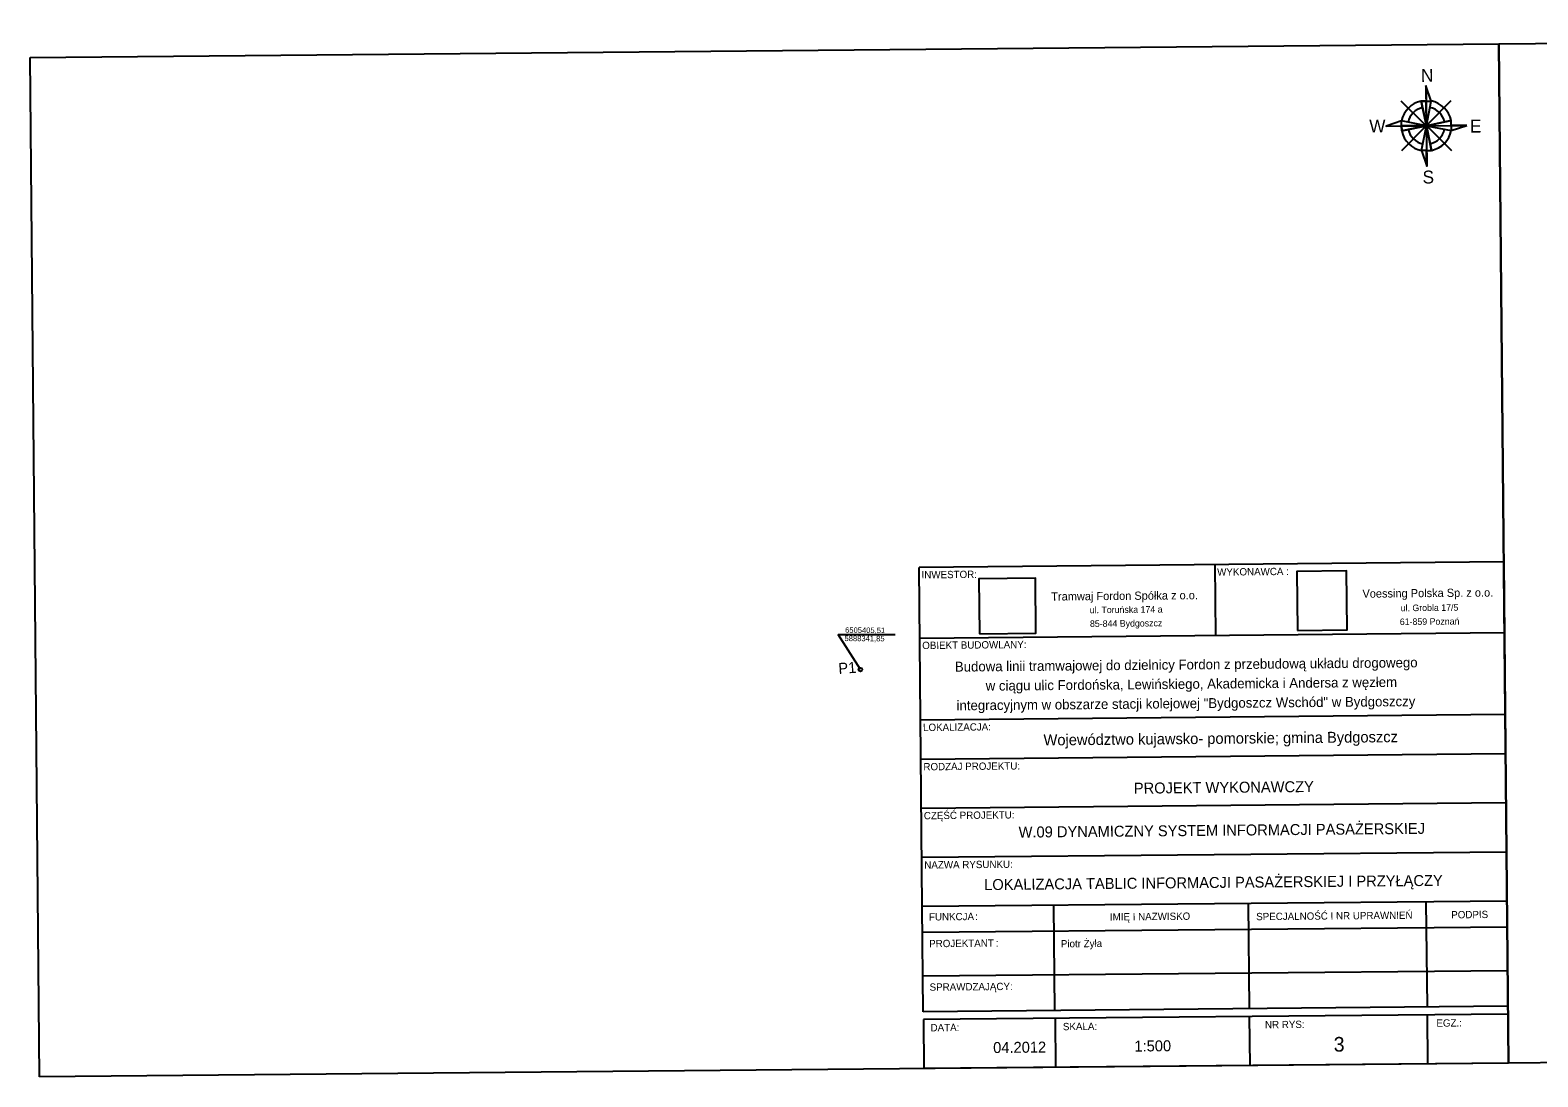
# Model space of a CAD drawing. Extents: x 6505045 to 6511721, y 5887996 to 5893535.
# Drawn here: x 6505291.9 to 6505498.2, y 5888286.1 to 5888429.3 of the extents above; entities that cross this region are included whole.
import ezdxf

# ---------------------------------------------------------------- set-up
doc = ezdxf.new("R2010")
doc.units = 0
for name, color, linetype in [('__legenda', 7, 'Continuous'), ('Default', 7, 'Continuous'), ('P_opisy', 7, 'Continuous'), ('P_przylacze', 7, 'Continuous'), ('P_tabela', 7, 'Continuous'), ('P_wsporzedne', 7, 'Continuous'), ('P_znak północy', 7, 'Continuous'), ('SA_Linie-020', 7, 'Continuous'), ('SA_Stempel_Text-020', 7, 'Continuous'), ('SA_Stempel_Text-030', 7, 'Continuous'), ('SA_Stempel_Text-035', 7, 'Continuous'), ('SA_Unterschrift_Text', 7, 'Continuous')]:
    doc.layers.add(name, color=color, linetype=linetype)

msp = doc.modelspace()

# ---------------------------------------------------------------- linework, layer by layer
at = {"layer": '__legenda'}
msp.add_lwpolyline([(6505465.32, 5888347.21), (6505472.12, 5888347.28), (6505472.04, 5888355.35), (6505465.24, 5888355.28)], close=True, dxfattribs=at)
at = {"layer": 'Default'}
msp.add_lwpolyline([(6505421.79, 5888346.75), (6505429.53, 5888346.82), (6505429.46, 5888354.35), (6505421.72, 5888354.28)], close=True, dxfattribs=at)
at = {"layer": 'P_przylacze'}
msp.add_circle((6505405.51, 5888341.85), 0.25, dxfattribs=at)
at = {"layer": 'P_tabela'}
for p, q in [((6505492.87, 5888427.46), (6505693.86, 5888429.33)), ((6505492.87, 5888427.46), (6505693.86, 5888429.33)), ((6505492.87, 5888427.46), (6505693.86, 5888429.33)), ((6505291.89, 5888425.58), (6505492.87, 5888427.46)), ((6505291.89, 5888425.58), (6505492.87, 5888427.46)), ((6505291.89, 5888425.58), (6505492.87, 5888427.46)), ((6505494.18, 5888288.01), (6505492.87, 5888427.46)), ((6505492.87, 5888427.46), (6505494.18, 5888288.01)), ((6505494.18, 5888288.01), (6505492.87, 5888427.46)), ((6505492.87, 5888427.46), (6505494.18, 5888288.01)), ((6505492.87, 5888427.46), (6505494.18, 5888288.01)), ((6505494.18, 5888288.01), (6505492.87, 5888427.46)), ((6505293.19, 5888286.13), (6505291.89, 5888425.58)), ((6505293.19, 5888286.13), (6505291.89, 5888425.58)), ((6505293.19, 5888286.13), (6505291.89, 5888425.58)), ((6505695.16, 5888289.89), (6505494.18, 5888288.01)), ((6505695.16, 5888289.89), (6505494.18, 5888288.01)), ((6505695.16, 5888289.89), (6505494.18, 5888288.01)), ((6505494.18, 5888288.01), (6505293.19, 5888286.13)), ((6505494.18, 5888288.01), (6505293.19, 5888286.13)), ((6505494.18, 5888288.01), (6505293.19, 5888286.13))]:
    msp.add_line(p, q, dxfattribs=at)
at = {"layer": 'P_wsporzedne'}
for p, q in [((6505405.51, 5888341.85), (6505402.48, 5888346.63)), ((6505402.48, 5888346.63), (6505410.25, 5888346.63))]:
    msp.add_line(p, q, dxfattribs=at)
at = {"layer": 'P_znak północy'}
for p, q in [((6505482.9, 5888421.78), (6505483, 5888410.74)), ((6505482.9, 5888421.78), (6505483, 5888410.74)), ((6505482.9, 5888421.78), (6505483, 5888410.74)), ((6505482.94, 5888416.26), (6505479.51, 5888419.64)), ((6505482.94, 5888416.26), (6505479.51, 5888419.64)), ((6505482.94, 5888416.26), (6505479.51, 5888419.64)), ((6505482.23, 5888419.63), (6505482.92, 5888419.64)), ((6505482.23, 5888419.63), (6505482.92, 5888419.64)), ((6505482.23, 5888419.63), (6505482.92, 5888419.64)), ((6505482.95, 5888416.26), (6505482.23, 5888419.63)), ((6505482.95, 5888416.26), (6505482.23, 5888419.63)), ((6505482.95, 5888416.26), (6505482.23, 5888419.63)), ((6505482.92, 5888419.64), (6505483.61, 5888419.64)), ((6505482.92, 5888419.64), (6505483.61, 5888419.64)), ((6505482.92, 5888419.64), (6505483.61, 5888419.64)), ((6505482.95, 5888416.27), (6505486.34, 5888419.71)), ((6505482.95, 5888416.27), (6505486.34, 5888419.71)), ((6505482.95, 5888416.27), (6505486.34, 5888419.71)), ((6505482.95, 5888416.26), (6505483.61, 5888419.64)), ((6505482.95, 5888416.26), (6505483.61, 5888419.64)), ((6505482.95, 5888416.26), (6505483.61, 5888419.64)), ((6505477.43, 5888416.21), (6505488.47, 5888416.31)), ((6505477.43, 5888416.21), (6505488.47, 5888416.31)), ((6505477.43, 5888416.21), (6505488.47, 5888416.31)), ((6505482.95, 5888416.26), (6505479.57, 5888416.92)), ((6505482.95, 5888416.26), (6505479.57, 5888416.92)), ((6505482.95, 5888416.26), (6505479.57, 5888416.92)), ((6505482.95, 5888416.27), (6505479.57, 5888412.81)), ((6505482.95, 5888416.27), (6505479.57, 5888412.81)), ((6505482.95, 5888416.27), (6505479.57, 5888412.81)), ((6505479.57, 5888416.23), (6505482.94, 5888416.26)), ((6505479.57, 5888416.23), (6505482.94, 5888416.26)), ((6505479.57, 5888416.23), (6505482.94, 5888416.26)), ((6505479.58, 5888415.54), (6505479.57, 5888416.23)), ((6505479.58, 5888415.54), (6505479.57, 5888416.23)), ((6505479.58, 5888415.54), (6505479.57, 5888416.23)), ((6505479.58, 5888415.54), (6505482.95, 5888416.26)), ((6505482.94, 5888416.26), (6505479.58, 5888415.54)), ((6505479.58, 5888415.54), (6505482.95, 5888416.26)), ((6505482.94, 5888416.26), (6505479.58, 5888415.54)), ((6505479.58, 5888415.54), (6505482.95, 5888416.26)), ((6505482.94, 5888416.26), (6505479.58, 5888415.54)), ((6505482.29, 5888412.87), (6505482.95, 5888416.26)), ((6505482.29, 5888412.87), (6505482.95, 5888416.26)), ((6505482.29, 5888412.87), (6505482.95, 5888416.26)), ((6505482.95, 5888416.26), (6505486.33, 5888416.98)), ((6505482.95, 5888416.26), (6505486.33, 5888416.98)), ((6505482.95, 5888416.26), (6505486.33, 5888416.98)), ((6505482.95, 5888416.27), (6505486.4, 5888412.88)), ((6505482.95, 5888416.27), (6505486.4, 5888412.88)), ((6505482.95, 5888416.27), (6505486.4, 5888412.88)), ((6505482.95, 5888416.26), (6505486.34, 5888415.6)), ((6505482.95, 5888416.26), (6505483.67, 5888412.89)), ((6505482.95, 5888416.26), (6505486.34, 5888415.6)), ((6505482.95, 5888416.26), (6505483.67, 5888412.89)), ((6505482.95, 5888416.26), (6505486.34, 5888415.6)), ((6505482.95, 5888416.26), (6505483.67, 5888412.89))]:
    msp.add_line(p, q, dxfattribs=at)
for points in [[(6505482.9, 5888421.78), (6505482.92, 5888419.64), (6505482.92, 5888419.64), (6505483.61, 5888419.64), (6505482.9, 5888421.78)], [(6505482.9, 5888421.78), (6505482.92, 5888419.64), (6505482.92, 5888419.64), (6505483.61, 5888419.64), (6505482.9, 5888421.78)], [(6505482.9, 5888421.78), (6505482.92, 5888419.64), (6505482.92, 5888419.64), (6505483.61, 5888419.64), (6505482.9, 5888421.78)], [(6505482.95, 5888416.27), (6505482.92, 5888419.64), (6505482.23, 5888419.63), (6505482.95, 5888416.26), (6505482.95, 5888416.27)], [(6505482.95, 5888416.27), (6505482.92, 5888419.64), (6505482.23, 5888419.63), (6505482.95, 5888416.26), (6505482.95, 5888416.27)], [(6505482.95, 5888416.27), (6505482.92, 5888419.64), (6505482.23, 5888419.63), (6505482.95, 5888416.26), (6505482.95, 5888416.27)], [(6505479.57, 5888416.23), (6505479.57, 5888416.92), (6505477.43, 5888416.21), (6505479.57, 5888416.23)], [(6505479.57, 5888416.23), (6505479.57, 5888416.92), (6505477.43, 5888416.21), (6505479.57, 5888416.23)], [(6505479.57, 5888416.23), (6505479.57, 5888416.92), (6505477.43, 5888416.21), (6505479.57, 5888416.23)], [(6505482.94, 5888416.26), (6505479.57, 5888416.23), (6505479.58, 5888415.54), (6505482.94, 5888416.26)], [(6505482.94, 5888416.26), (6505479.57, 5888416.23), (6505479.58, 5888415.54), (6505482.94, 5888416.26)], [(6505482.94, 5888416.26), (6505479.57, 5888416.23), (6505479.58, 5888415.54), (6505482.94, 5888416.26)], [(6505482.95, 5888416.26), (6505482.95, 5888416.26), (6505482.96, 5888416.26), (6505486.33, 5888416.29), (6505486.33, 5888416.98), (6505482.95, 5888416.26)], [(6505482.95, 5888416.26), (6505482.95, 5888416.26), (6505482.96, 5888416.26), (6505486.33, 5888416.29), (6505486.33, 5888416.98), (6505482.95, 5888416.26)], [(6505482.95, 5888416.26), (6505482.95, 5888416.26), (6505482.96, 5888416.26), (6505486.33, 5888416.29), (6505486.33, 5888416.98), (6505482.95, 5888416.26)], [(6505482.98, 5888412.88), (6505483.67, 5888412.89), (6505482.95, 5888416.25), (6505482.98, 5888412.88)], [(6505482.98, 5888412.88), (6505483.67, 5888412.89), (6505482.95, 5888416.25), (6505482.98, 5888412.88)], [(6505482.98, 5888412.88), (6505483.67, 5888412.89), (6505482.95, 5888416.25), (6505482.98, 5888412.88)], [(6505488.47, 5888416.31), (6505486.33, 5888416.29), (6505486.34, 5888415.6), (6505488.47, 5888416.31)], [(6505488.47, 5888416.31), (6505486.33, 5888416.29), (6505486.34, 5888415.6), (6505488.47, 5888416.31)], [(6505488.47, 5888416.31), (6505486.33, 5888416.29), (6505486.34, 5888415.6), (6505488.47, 5888416.31)], [(6505482.98, 5888412.88), (6505482.29, 5888412.87), (6505483, 5888410.74), (6505482.98, 5888412.88)], [(6505482.98, 5888412.88), (6505482.29, 5888412.87), (6505483, 5888410.74), (6505482.98, 5888412.88)], [(6505482.98, 5888412.88), (6505482.29, 5888412.87), (6505483, 5888410.74), (6505482.98, 5888412.88)]]:
    msp.add_lwpolyline(points, dxfattribs=at)
for centre, radius, start, end in [((6505482.95, 5888416.26), 3.45, 102.0474, 168.9738), ((6505482.95, 5888416.26), 3.45, 102.0474, 168.9738), ((6505482.95, 5888416.26), 3.45, 102.0474, 168.9738), ((6505482.96, 5888416.26), 3.45, 12.0554, 79.0163), ((6505482.96, 5888416.26), 3.45, 12.0554, 79.0163), ((6505482.96, 5888416.26), 3.45, 12.0554, 79.0163), ((6505482.95, 5888416.27), 2.53, 102.1671, 169.2958), ((6505482.95, 5888416.27), 2.53, 102.1671, 169.2958), ((6505482.95, 5888416.27), 2.53, 102.1671, 169.2958), ((6505482.95, 5888416.27), 2.53, 11.7816, 78.9353), ((6505482.95, 5888416.27), 2.53, 11.7816, 78.9353), ((6505482.95, 5888416.27), 2.53, 11.7816, 78.9353), ((6505482.95, 5888416.26), 3.45, 192.0538, 259.0158), ((6505482.95, 5888416.26), 3.45, 192.0538, 259.0158), ((6505482.95, 5888416.26), 3.45, 192.0538, 259.0158), ((6505482.95, 5888416.27), 2.53, 192.3917, 259.0318), ((6505482.95, 5888416.27), 2.53, 192.3917, 259.0318), ((6505482.95, 5888416.27), 2.53, 192.3917, 259.0318), ((6505482.95, 5888416.27), 2.53, 282.0081, 348.6723), ((6505482.95, 5888416.27), 2.53, 282.0081, 348.6723), ((6505482.95, 5888416.27), 2.53, 282.0081, 348.6723), ((6505482.96, 5888416.26), 3.45, 282.0538, 349.0163), ((6505482.96, 5888416.26), 3.45, 282.0538, 349.0163), ((6505482.96, 5888416.26), 3.45, 282.0538, 349.0163)]:
    msp.add_arc(centre, radius, start, end, dxfattribs=at)
at = {"layer": 'SA_Linie-020'}
for p, q in [((6505493.54, 5888356.58), (6505413.54, 5888355.83)), ((6505413.97, 5888309.42), (6505413.54, 5888355.83)), ((6505453.99, 5888356.21), (6505454.08, 5888346.55)), ((6505493.54, 5888356.58), (6505494.1, 5888295.79)), ((6505413.63, 5888346.17), (6505493.63, 5888346.92)), ((6505493.73, 5888335.7), (6505413.73, 5888334.95)), ((6505493.78, 5888330.32), (6505413.78, 5888329.57)), ((6505493.84, 5888323.6), (6505413.85, 5888322.86)), ((6505493.84, 5888323.6), (6505413.85, 5888322.86)), ((6505493.91, 5888316.88), (6505413.91, 5888316.14)), ((6505493.97, 5888310.16), (6505413.97, 5888309.42)), ((6505414.11, 5888295.04), (6505413.97, 5888309.42)), ((6505432.13, 5888295.21), (6505431.99, 5888309.59)), ((6505458.57, 5888309.84), (6505458.7, 5888295.46)), ((6505482.9, 5888310.06), (6505483.04, 5888295.69)), ((6505494, 5888306.6), (6505414.01, 5888305.86)), ((6505494.06, 5888300.64), (6505414.06, 5888299.9)), ((6505494.1, 5888295.79), (6505414.11, 5888295.04)), ((6505494.11, 5888294.73), (6505414.12, 5888293.98)), ((6505414.12, 5888293.98), (6505414.18, 5888287.26)), ((6505432.14, 5888294.15), (6505432.2, 5888287.43)), ((6505458.71, 5888294.4), (6505458.78, 5888287.68)), ((6505483.05, 5888294.63), (6505483.11, 5888287.91)), ((6505494.11, 5888294.73), (6505494.18, 5888288.01)), ((6505494.18, 5888288.01), (6505414.18, 5888287.26))]:
    msp.add_line(p, q, dxfattribs=at)

# ---------------------------------------------------------------- texts
at = {"layer": 'P_opisy'}
msp.add_text('P1', height=1.501, rotation=3.877, dxfattribs=at).set_placement((6505402.54, 5888341.25))
at = {"layer": 'P_wsporzedne'}
for s, p in [('6505405,51', (6505403.41, 5888346.88)), ('5888341,85', (6505403.33, 5888345.75))]:
    msp.add_text(s, height=0.751, rotation=359.6048, dxfattribs=at).set_placement(p)
at = {"layer": 'P_znak północy'}
for s, p in [('N', (6505482.22, 5888422.26)), ('N', (6505482.22, 5888422.26)), ('N', (6505482.22, 5888422.26)), ('W', (6505475.15, 5888415.33)), ('W', (6505475.15, 5888415.33)), ('W', (6505475.15, 5888415.33)), ('E', (6505488.93, 5888415.32)), ('E', (6505488.93, 5888415.32)), ('E', (6505488.93, 5888415.32)), ('S', (6505482.44, 5888408.35)), ('S', (6505482.44, 5888408.35)), ('S', (6505482.44, 5888408.35))]:
    msp.add_text(s, height=1.76, rotation=0.535, dxfattribs=at).set_placement(p)
at = {"layer": 'SA_Stempel_Text-020'}
for s, p in [('WYKONAWCA :', (6505454.33, 5888354.7)), ('INWESTOR:', (6505413.88, 5888354.32)), ('OBIEKT BUDOWLANY:', (6505413.97, 5888344.66)), ('LOKALIZACJA:', (6505414.08, 5888333.44)), ('RODZAJ PROJEKTU:', (6505414.13, 5888328.06)), ('CZĘŚĆ PROJEKTU:', (6505414.19, 5888321.37)), ('NAZWA RYSUNKU:', (6505414.25, 5888314.62)), ('FUNKCJA', (6505414.89, 5888307.52)), (':', (6505421.22, 5888307.58)), ('IMIĘ I NAZWISKO', (6505439.65, 5888307.52)), ('SPECJALNOŚĆ I NR UPRAWNIEŃ', (6505459.67, 5888307.56)), ('PODPIS', (6505486.36, 5888307.81)), ('PROJEKTANT', (6505414.92, 5888303.86)), (':', (6505424.05, 5888303.95)), ('SPRAWDZAJĄCY:', (6505414.98, 5888297.91)), ('NR RYS:', (6505460.87, 5888292.77)), ('EGZ.:', (6505484.33, 5888292.99)), ('DATA:', (6505415.11, 5888292.36)), ('SKALA:', (6505433.22, 5888292.51))]:
    msp.add_text(s, height=1, rotation=0.535, dxfattribs=at).set_placement(p)
at = {"layer": 'SA_Stempel_Text-030'}
for s, height, p in [('3', 2, (6505470.28, 5888289.58)), ('04.2012', 1.5, (6505423.68, 5888289.39)), ('1:500', 1.5, (6505443.01, 5888289.59))]:
    msp.add_text(s, height=height, rotation=0.535, dxfattribs=at).set_placement(p)
at = {"layer": 'SA_Stempel_Text-035'}
for s, height, p in [('Budowa linii tramwajowej do dzielnicy Fordon z przebudową układu drogowego', 1.35, (6505418.44, 5888341.57)), ('w ciągu ulic Fordońska, Lewińskiego, Akademicka i Andersa z węzłem', 1.35, (6505422.66, 5888338.96)), ('integracyjnym w obszarze stacji kolejowej "Bydgoszcz Wschód" w Bydgoszczy', 1.35, (6505418.67, 5888336.27)), ('Województwo kujawsko- pomorskie; gmina Bydgoszcz', 1.5, (6505430.57, 5888331.47)), ('PROJEKT WYKONAWCZY', 1.5, (6505442.93, 5888324.87)), ('W.09 DYNAMICZNY SYSTEM INFORMACJI PASAŻERSKIEJ', 1.5, (6505427.16, 5888318.86)), ('LOKALIZACJA TABLIC INFORMACJI PASAŻERSKIEJ I PRZYŁĄCZY', 1.5, (6505422.45, 5888311.68))]:
    msp.add_text(s, height=height, rotation=0.535, dxfattribs=at).set_placement(p)
at = {"layer": 'SA_Unterschrift_Text'}
for s, height, p in [('Tramwaj Fordon Spółka z o.o.', 1.125, (6505431.63, 5888351.29)), ('Voessing Polska Sp. z o.o.', 1.125, (6505474.21, 5888351.68)), ('ul. Toruńska 174 a', 0.9, (6505436.89, 5888349.56)), ('ul. Grobla 17/5', 0.9, (6505479.44, 5888349.83)), ('85-844 Bydgoszcz', 0.9, (6505436.92, 5888347.68)), ('61-859 Poznań', 0.9, (6505479.32, 5888347.94)), ('Piotr Żyła', 1, (6505432.94, 5888303.84))]:
    msp.add_text(s, height=height, rotation=0.535, dxfattribs=at).set_placement(p)

doc.saveas('drawing.dxf')
